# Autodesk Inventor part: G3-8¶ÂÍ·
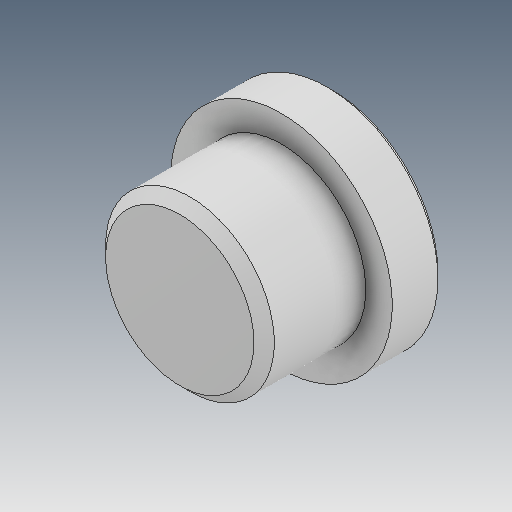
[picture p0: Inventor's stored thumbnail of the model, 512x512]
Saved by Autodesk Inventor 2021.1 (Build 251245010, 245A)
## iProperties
Created: 2021-05
Part Number: G3-8¶ÂÍ·
Material: Ogólny
Document SubType Name: Modeling
Designer: user
Density: 1 g/cm^3
Appearance: Domyślna
Author: user
Revision Number: ÈÎºÎ
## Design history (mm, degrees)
feature "µ¹½Ç2"
node "Bryła1"
